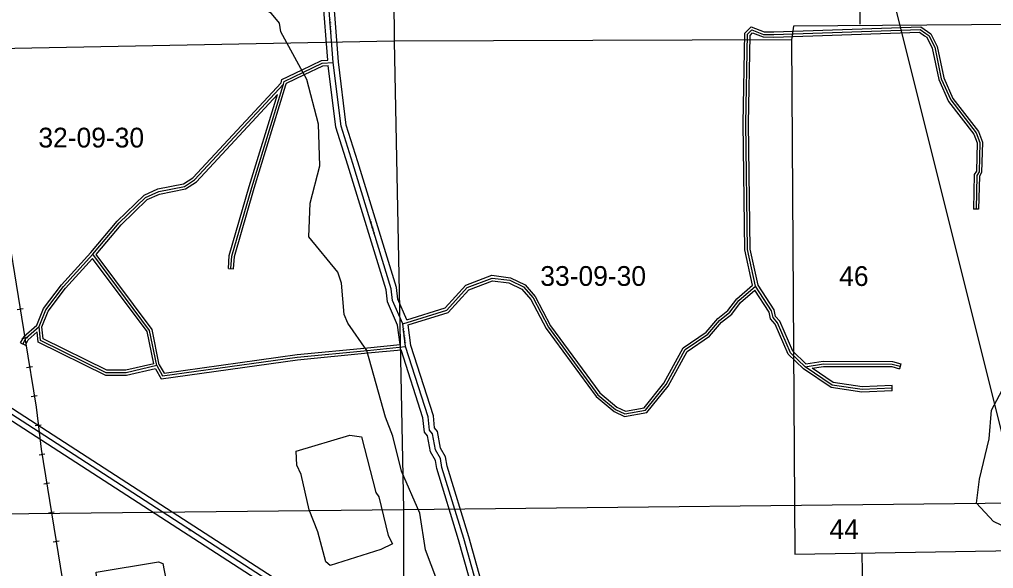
# Model space of a CAD drawing. Extents: x 418523 to 616617, y 1878279 to 2196743.
# Drawn here: x 559247 to 570344, y 1939235 to 1945489 of the extents above; entities that cross this region are included whole.
import ezdxf

# ---------------------------------------------------------------- set-up
doc = ezdxf.new("R2010")
doc.units = 0
for name, color, linetype in [('Level 1', 7, 'Continuous'), ('Level 13', 7, 'Continuous'), ('Level 14', 7, 'Continuous'), ('Level 2', 7, 'Continuous'), ('Level 31', 7, 'Continuous'), ('Level 32', 7, 'Continuous'), ('Level 34', 7, 'Continuous'), ('Level 37', 7, 'Continuous'), ('Level 5', 7, 'Continuous')]:
    doc.layers.add(name, color=color, linetype=linetype)

msp = doc.modelspace()

# ---------------------------------------------------------------- linework, layer by layer
at = {"layer": 'Level 1'}
for p, q in [((563498.761, 1950526.305), (563513.797, 1945243.459)), ((568769.441, 1950592.162), (568822.676, 1945437.311)), ((569145.641, 1945954.963), (571104.953, 1938088.985)), ((568065.987, 1945414.76), (568043.759, 1945256.718)), ((572045.49, 1945443.091), (568065.987, 1945414.76)), ((563513.797, 1945243.459), (558223.052, 1945139.621)), ((568043.759, 1945256.718), (563513.797, 1945243.459)), ((563513.797, 1945243.459), (563622.845, 1939908.403)), ((568043.759, 1945256.718), (568082.051, 1939397.52)), ((563622.845, 1939908.403), (573851.894, 1940018.709)), ((558344.174, 1939850.566), (563622.845, 1939908.403)), ((563622.845, 1939908.403), (563619.866, 1934617.7)), ((568082.051, 1939397.52), (572035.581, 1939463.921)), ((568842.722, 1939404.055), (568918.577, 1934703.401))]:
    msp.add_line(p, q, dxfattribs=at)
at = {"layer": 'Level 13'}
for p, q in [((562821.593, 1944999.369), (562756.996, 1945825.017)), ((563646.429, 1941762.631), (563613.731, 1942021.267))]:
    msp.add_line(p, q, dxfattribs=at)
for points in [[(559469.888, 1940786.39), (556696.12, 1942581.826), (556188.721, 1942966.485), (555315.458, 1943802.711), (554875.168, 1944329.028), (554867.048, 1944378.871), (554472.45, 1945001.799)], [(563613.731, 1942021.267), (563497.85, 1942288.476), (563481.671, 1942421.976), (563043.52, 1943848.585), (562911.217, 1944274.026), (562821.593, 1944999.369)], [(564687.444, 1938291.918), (564555.358, 1938692.623), (564307.599, 1939576.905), (564059.665, 1940386.277), (564043.081, 1940486.322), (563985.212, 1940586.47), (563952.323, 1940769.831), (563919.081, 1940811.734), (563902.941, 1940961.961), (563646.429, 1941762.631)], [(563811.423, 1938019.181), (563295.507, 1938354.303), (562879.371, 1938580.451), (559469.888, 1940786.39)]]:
    msp.add_lwpolyline(points, dxfattribs=at)
at = {"layer": 'Level 14'}
for p, q in [((562759.357, 1945025.605), (562697.3, 1945818.785)), ((562881.308, 1945005.39), (562818.249, 1945811.365)), ((563582.929, 1941786.534), (563555.279, 1942005.247)), ((563705.262, 1941775.656), (563675.729, 1942009.261))]:
    msp.add_line(p, q, dxfattribs=at)
for points in [[(559437.284, 1940736.02), (556661.646, 1942532.666), (556149.72, 1942920.758), (555271.565, 1943761.668), (554818.592, 1944303.145), (554809.799, 1944357.121), (554419.556, 1944973.172)], [(559502.492, 1940836.76), (556730.593, 1942630.986), (556227.724, 1943012.211), (555359.352, 1943843.755), (554931.744, 1944354.911), (554924.297, 1944400.621), (554525.345, 1945030.423)], [(563555.278, 1942005.247), (563439.333, 1942272.603), (563422.747, 1942409.461), (562986.194, 1943830.867), (562852.328, 1944261.336), (562765.277, 1944965.852)], [(563659.302, 1942066.993), (563556.367, 1942304.351), (563540.595, 1942434.491), (563100.846, 1943866.301), (562970.106, 1944286.714), (562881.308, 1945005.391)], [(564628.259, 1938279.811), (564497.948, 1938675.127), (564250.016, 1939560.021), (564001.125, 1940372.524), (563985.672, 1940465.747), (563928.007, 1940565.541), (563895.931, 1940744.372), (563861.277, 1940788.051), (563843.936, 1940949.475), (563594.711, 1941727.401)], [(564740.286, 1938323.27), (564612.768, 1938710.118), (564365.181, 1939593.788), (564118.206, 1940400.031), (564100.491, 1940506.896), (564042.417, 1940607.398), (564008.716, 1940795.29), (563976.883, 1940835.416), (563961.946, 1940974.446), (563705.262, 1941775.656)], [(563861.994, 1938057.88), (563326.221, 1938405.901), (562910.038, 1938632.074), (559502.481, 1940836.766)], [(563811.341, 1937947.684), (563264.793, 1938302.706), (562848.705, 1938528.827), (559437.295, 1940736.013)]]:
    msp.add_lwpolyline(points, dxfattribs=at)
at = {"layer": 'Level 31'}
for p, q in [((559286.734, 1941791.271), (559310.996, 1941839.571)), ((563213.458, 1941720.081), (563646.429, 1941762.631))]:
    msp.add_line(p, q, dxfattribs=at)
for points in [[(567633.101, 1942452.516), (567542.64, 1942869.475), (567521.311, 1944303.395), (567540.901, 1945320.474)], [(567540.901, 1945320.474), (567590.875, 1945370.174), (567724.126, 1945319.671), (567840.984, 1945319.391)], [(567840.984, 1945319.391), (569508.253, 1945373.26), (569574.2, 1945329.104)], [(569574.2, 1945329.104), (569608.124, 1945306.477), (569674.497, 1945172.863), (569748.6, 1944814.132), (569856.321, 1944572.052), (570146.963, 1944196.452), (570188.628, 1944087.625), (570179.277, 1943754.181), (570154.093, 1943712.783), (570144.626, 1943329.156)], [(562480.894, 1944888.591), (562696.458, 1944991.686), (562821.593, 1944999.369)], [(562254.127, 1944750.981), (562262.469, 1944784.416), (562480.894, 1944888.591)], [(560081.446, 1942814.321), (560382.481, 1943172.096), (560683.337, 1943462.964), (560833.401, 1943529.488), (561125.392, 1943586.919), (561242.449, 1943661.53), (562254.127, 1944750.981)], [(561656.511, 1942651.703), (561665.131, 1942793.505), (561892.29, 1943576.588), (562254.127, 1944750.981)], [(559470.501, 1941990.796), (559546.268, 1942182.241), (559747.039, 1942448.635), (560081.446, 1942814.321)], [(560811.446, 1941545.473), (560729.274, 1941945.7), (560081.446, 1942814.321)], [(563613.731, 1942021.267), (564114.311, 1942178.203), (564348.69, 1942436.174), (564632.235, 1942543.837), (564832.244, 1942518.25), (564990.528, 1942442.946), (565098.512, 1942317.586), (565272.676, 1941983.69), (565837.359, 1941215.006), (566037.031, 1941047.966), (566145.523, 1940997.517), (566379.05, 1941038.405), (566613.184, 1941329.846), (566831.061, 1941729.332), (567089.676, 1941903.622), (567223.757, 1942061.487), (567340.529, 1942153.209), (567440.886, 1942286.063), (567633.101, 1942452.516)], [(568197.467, 1941533.681), (568031.116, 1941692.629), (567882.034, 1942034.816), (567832.315, 1942093.481), (567815.662, 1942168.433), (567633.101, 1942452.516)], [(559310.996, 1941839.571), (559320.253, 1941857.73), (559470.501, 1941990.796)], [(560811.446, 1941545.473), (560461.254, 1941462.74), (560236.088, 1941463.688), (559486.917, 1941832.201), (559470.501, 1941990.796)], [(560811.446, 1941545.473), (560877.837, 1941428.57), (562412.314, 1941641.013), (563213.458, 1941720.081)], [(568197.467, 1941533.681), (568406.198, 1941566.641), (569189.671, 1941564.424), (569281.394, 1941539.116)], [(569189.024, 1941289.507), (568846.946, 1941273.586), (568505.346, 1941324.579), (568197.467, 1941533.681)]]:
    msp.add_lwpolyline(points, dxfattribs=at)
at = {"layer": 'Level 32'}
for p, q in [((570174.617, 1943328.416), (570114.634, 1943329.896)), ((561626.566, 1942653.523), (561686.456, 1942649.882)), ((559259.926, 1941804.736), (559284.188, 1941853.037)), ((559259.926, 1941804.736), (559313.543, 1941777.804)), ((559313.543, 1941777.804), (559337.805, 1941826.105)), ((563210.524, 1941749.936), (563582.929, 1941786.534)), ((563216.392, 1941690.223), (563594.711, 1941727.401)), ((569289.373, 1941568.036), (569273.414, 1941510.196)), ((569190.419, 1941259.539), (569187.63, 1941319.476))]:
    msp.add_line(p, q, dxfattribs=at)
for points in [[(567511.14, 1945333.186), (567583.429, 1945405.08), (567729.654, 1945349.659), (567840.536, 1945349.392)], [(567840.536, 1945349.393), (569516.926, 1945403.556), (569590.891, 1945354.032)], [(567600.01, 1942463.545), (567512.686, 1942866.037), (567491.306, 1944303.46), (567511.14, 1945333.186)], [(567661.27, 1942464.174), (567572.592, 1942872.912), (567551.316, 1944303.329), (567570.663, 1945307.76)], [(567570.663, 1945307.76), (567598.321, 1945335.268), (567718.596, 1945289.684), (567841.433, 1945289.389)], [(567841.433, 1945289.388), (569499.579, 1945342.963), (569557.508, 1945304.176)], [(569557.554, 1945304.145), (569584.817, 1945285.961), (569645.902, 1945162.992), (569719.874, 1944804.893), (569830.381, 1944556.553), (570120.527, 1944181.592), (570158.471, 1944082.485), (570149.511, 1943762.976), (570124.299, 1943721.531), (570114.634, 1943329.896)], [(569590.846, 1945354.063), (569631.431, 1945326.994), (569703.093, 1945182.733), (569777.326, 1944823.371), (569882.26, 1944587.552), (570173.398, 1944211.312), (570218.784, 1944092.764), (570209.043, 1943745.386), (570183.887, 1943704.035), (570174.617, 1943328.416)], [(562467.95, 1944915.656), (562688.786, 1945021.271), (562759.357, 1945025.604)], [(562493.838, 1944861.527), (562704.13, 1944962.099), (562765.277, 1944965.853)], [(562226.889, 1944765.736), (562236.785, 1944805.404), (562467.979, 1944915.671)], [(562283.039, 1944742.927), (562288.153, 1944763.427), (562493.809, 1944861.513)], [(560058.89, 1942834.109), (560360.518, 1943192.593), (560666.312, 1943488.233), (560824.314, 1943558.276), (561114.045, 1943615.262), (561223.081, 1943684.761), (562226.889, 1944765.736)], [(561686.456, 1942649.882), (561694.874, 1942788.352), (561921.034, 1943567.991), (562283.039, 1944742.926)], [(560119.709, 1942813.197), (560404.443, 1943151.601), (560700.362, 1943437.696), (560842.486, 1943500.7), (561136.741, 1943558.575), (561261.816, 1943638.297), (562186.82, 1944634.408)], [(561626.566, 1942653.523), (561635.387, 1942798.656), (561863.546, 1943585.184), (562186.821, 1944634.408)], [(559445.244, 1942008.501), (559519.866, 1942197.056), (559723.938, 1942467.829), (560058.889, 1942834.108)], [(559501.099, 1941986.581), (559572.67, 1942167.426), (559770.139, 1942429.44), (560079.095, 1942767.292)], [(560776.201, 1941567.972), (560701.231, 1941933.121), (560079.095, 1942767.292)], [(560839.88, 1941556.157), (560757.318, 1941958.279), (560119.71, 1942813.197)], [(563659.302, 1942066.993), (564097.576, 1942204.396), (564331.319, 1942461.67), (564628.599, 1942574.547), (564840.805, 1942547.4), (565009.13, 1942467.32), (565123.508, 1942334.536), (565298.214, 1941999.601), (565859.39, 1941235.69), (566053.256, 1941073.506), (566149.63, 1941028.693), (566362.742, 1941066.006), (566588.124, 1941346.555), (566808.226, 1941750.121), (567069.484, 1941926.192), (567202.848, 1942083.212), (567318.936, 1942174.398), (567418.854, 1942306.671), (567600.01, 1942463.545)], [(563675.728, 1942009.262), (564131.046, 1942152.01), (564366.061, 1942410.679), (564635.871, 1942513.126), (564823.683, 1942489.1), (564971.926, 1942418.573), (565073.517, 1942300.635), (565247.138, 1941967.779), (565815.328, 1941194.321), (566020.806, 1941022.425), (566141.416, 1940966.341), (566395.358, 1941010.804), (566638.244, 1941313.138), (566853.895, 1941708.544), (567109.867, 1941881.053), (567244.666, 1942039.762), (567362.121, 1942132.021), (567462.917, 1942265.456), (567626.576, 1942407.177)], [(568178.547, 1941510.265), (568006.024, 1941675.11), (567856.294, 1942018.786), (567804.636, 1942079.74), (567787.536, 1942156.711), (567626.576, 1942407.177)], [(568207.457, 1941565.631), (568056.207, 1941710.148), (567907.775, 1942050.844), (567859.994, 1942107.224), (567843.79, 1942180.156), (567661.27, 1942464.174)], [(559284.269, 1941853.198), (559296.108, 1941876.42), (559445.245, 1942008.501)], [(560776.201, 1941567.971), (560457.821, 1941492.756), (560243.127, 1941493.66), (559515.051, 1941851.797), (559501.098, 1941986.582)], [(559337.723, 1941825.945), (559344.399, 1941839.04), (559446.673, 1941929.616)], [(560796.463, 1941511.106), (560464.687, 1941432.724), (560229.05, 1941433.716), (559458.785, 1941812.606), (559446.674, 1941929.616)], [(560839.881, 1941556.157), (560893.877, 1941461.078), (562408.781, 1941670.811), (563210.511, 1941749.936)], [(560796.463, 1941511.106), (560861.797, 1941396.062), (562415.846, 1941611.215), (563216.404, 1941690.225)], [(569190.419, 1941259.539), (568845.415, 1941243.482), (568494.15, 1941295.917), (568178.548, 1941510.265)], [(568207.457, 1941565.631), (568403.886, 1941596.648), (569193.776, 1941594.413), (569289.373, 1941568.036)], [(568277.076, 1941515.879), (568408.511, 1941536.634), (569185.566, 1941534.435), (569273.414, 1941510.196)], [(569187.63, 1941319.476), (568848.479, 1941303.691), (568516.541, 1941353.241), (568277.076, 1941515.879)]]:
    msp.add_lwpolyline(points, dxfattribs=at)
at = {"layer": 'Level 37'}
for p, q in [((559220.671, 1942186.001), (559287.145, 1942196.787)), ((559274.306, 1941855.462), (559340.779, 1941866.249)), ((559327.974, 1941524.926), (559394.447, 1941535.72)), ((559381.646, 1941194.393), (559448.118, 1941205.186)), ((559426.666, 1940864.056), (559493.529, 1940872.072)), ((559469.437, 1940530.561), (559535.909, 1940541.365)), ((559523.161, 1940200.036), (559589.631, 1940210.84)), ((559576.882, 1939869.511), (559643.352, 1939880.316)), ((559630.604, 1939538.988), (559697.074, 1939549.791))]:
    msp.add_line(p, q, dxfattribs=at)
msp.add_lwpolyline([(554866.266, 1969249.629), (554867.125, 1969244.323), (555789.684, 1963551.706), (557100.687, 1955463.798), (557725.337, 1951612.51), (558452.601, 1947129.67), (559310.996, 1941839.571), (559435.7, 1941071.581), (559469.888, 1940786.39), (559492.892, 1940596.141), (560291.277, 1935684.071), (560315.664, 1935534.186)], dxfattribs=at)
at = {"layer": 'Level 5'}
for points in [[(564128.021, 1938623.19), (564103.867, 1938890.046), (564054.075, 1938965.236), (563872.244, 1939449.336), (563806.897, 1939866.355), (563600.026, 1940342.173), (563501.258, 1940742.651), (563418.583, 1940959.656), (563204.287, 1941718.981), (562988.528, 1942028.116), (562947.166, 1942128.287), (562914.971, 1942486.846), (562873.677, 1942612.018), (562541.535, 1943013.243), (562559.41, 1943396.652), (562669.156, 1943821.484), (562654.019, 1944296.685), (562522.269, 1944805.626), (562223.894, 1945348.474), (562207.552, 1945448.536), (562116.179, 1945557.208), (561650.255, 1945842.148), (561176.289, 1946218.821)], [(571432.721, 1939249.991), (570342.321, 1939770.339), (570151.244, 1939979.371), (570185.471, 1940254.368), (570295.317, 1940712.511), (570321.373, 1941037.569), (570564.592, 1941495.283)]]:
    msp.add_lwpolyline(points, dxfattribs=at)
for points in [[(562787.933, 1939269.397), (562738.041, 1939311.247), (562647.455, 1939653.335), (562548.209, 1939903.749), (562457.811, 1940304.187), (562408.119, 1940412.73), (562400.306, 1940571.113), (563009.447, 1940752.586), (563142.76, 1940735.456), (563307.463, 1940101.374), (563340.644, 1940051.253), (563447.613, 1939609.064), (563497.305, 1939517.202), (563363.733, 1939450.939), (562787.933, 1939269.397)], [(560324.269, 1937893.472), (560217.371, 1938343.971), (560185.493, 1938810.902), (560136.059, 1938994.466), (560120.046, 1939194.601), (560828.99, 1939309.022), (560878.971, 1939292.183), (560952.798, 1938916.825), (560943.741, 1938691.769), (561066.663, 1938032.806), (560949.821, 1937991.483), (560324.269, 1937893.472)]]:
    msp.add_lwpolyline(points, close=True, dxfattribs=at)

# ---------------------------------------------------------------- texts
at = {"layer": 'Level 2'}
for s, p in [('32-09-30', (559462.052, 1944031.078)), ('33-09-30', (565180.75, 1942454.661)), ('46', (568585.899, 1942453.457)), ('44', (568475.965, 1939569.688))]:
    msp.add_text(s, height=225, dxfattribs=at).set_placement(p)
at = {"layer": 'Level 34'}
for s, rotation, p in [('US HWY 1', 274.4728028, (562770.864, 1945487.521)), ('US HWY 1', 287.0724028, (563228.176, 1943204.774)), ('US HWY 1', 277.2045639, (563608.08, 1941966.313)), ('I- 95', 327.0963694, (561137.826, 1939692.345))]:
    msp.add_text(s, height=25, rotation=rotation, dxfattribs=at).set_placement(p)

doc.saveas('drawing.dxf')
